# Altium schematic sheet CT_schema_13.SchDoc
size 274 x 160 mm
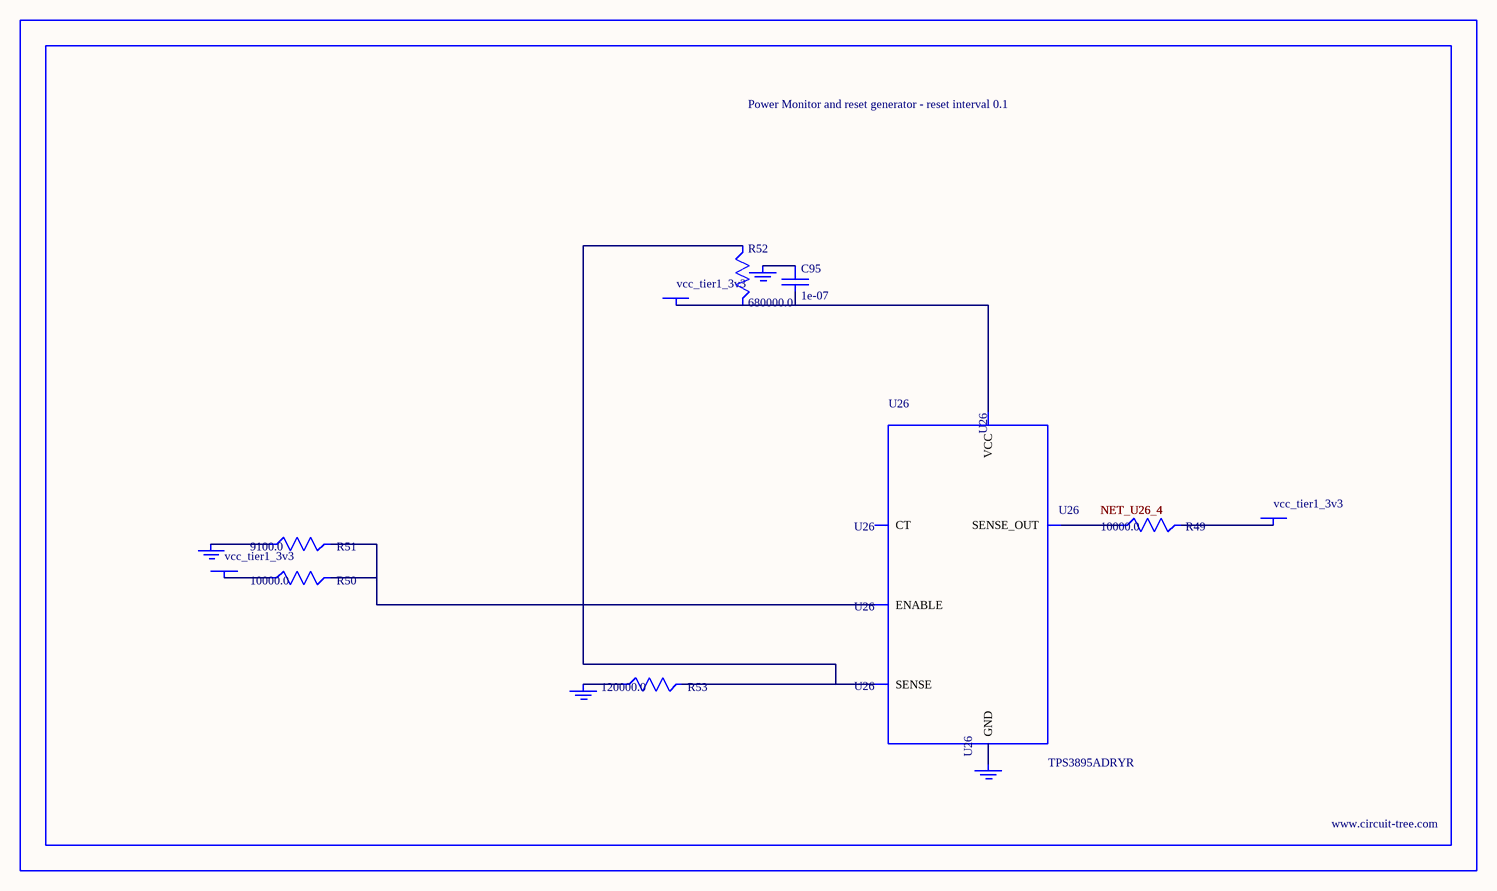
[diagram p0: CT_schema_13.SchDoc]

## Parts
BORDER12  (no value)
C95  1e-07  [C0402]
GND_INSTANCE_12_0  (no value)
GND_INSTANCE_12_1  (no value)
GND_INSTANCE_12_2  (no value)
GND_INSTANCE_12_3  (no value)
POWER_INSTANCE_12_0  vcc_tier1_3v3
POWER_INSTANCE_12_1  vcc_tier1_3v3
POWER_INSTANCE_12_2  vcc_tier1_3v3
R49  10000.0  [R0603]
R50  10000.0  [R0603]
R51  9100.0  [R0603]
R52  680000.0  [R0603]
R53  120000.0  [R0603]
U26  TPS3895ADRYR  [SON-6]

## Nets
NetC95_1: C95.1 GND_INSTANCE_12_2.0(GND)
NetC95_2: C95.2 POWER_INSTANCE_12_2.0(PWR) R52.2 U26.6(VCC)
NetGND_INSTANCE_12_0_0: GND_INSTANCE_12_0.0(GND) R51.1
NetGND_INSTANCE_12_1_0: GND_INSTANCE_12_1.0(GND) R53.1
NetGND_INSTANCE_12_3_0: GND_INSTANCE_12_3.0(GND) U26.2(GND)
NetPOWER_INSTANCE_12_0_0: POWER_INSTANCE_12_0.0(PWR) R50.1
NetPOWER_INSTANCE_12_1_0: POWER_INSTANCE_12_1.0(PWR) R49.2
NetR49_1: R49.1 U26.4(SENSE_OUT)
NetR50_2: R50.2 R51.2 U26.1(ENABLE)
NetR52_1: R52.1 R53.2 U26.3(SENSE)

Not connected (* = marked no-connect by the designer): U26 5(CT)

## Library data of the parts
BORDER12 = BORDER_PAGE12
C95 = C0402C104K3RACTU
GND_INSTANCE_12_0-GND_INSTANCE_12_3 = GND
POWER_INSTANCE_12_0-POWER_INSTANCE_12_2 = PWR
R49 R50 = RC0603JR-0710KL
R51 = RC0603JR-079K1L
R52 = RC0603JR-07680KL
R53 = RC0603JR-07120KL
